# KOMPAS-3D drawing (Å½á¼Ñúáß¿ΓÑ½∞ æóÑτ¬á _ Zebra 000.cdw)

Views: Разрез А-А, Вид 3, Диметрия, Вид 4
Referenced files in D:\работа\Чертежи\Компенсатор\Пламегаситель Свечка\: ДТК.a3d, Компенсатор.m3d, Колпак.m3d, Пламегаситель Свечка _ Zebra 000.cdw
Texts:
  Zebra 000
  Пламегаситель "Свечка"
  Александр
  Колпак
  Компенсатор
  Zebra 002
  ТДК
  Zebra 001
  Лит-Масса-Масштаб
  Материал-Предприятие
  Title Specification
  Body Specification ( left align )
  Body Specificaton ( centered )
  Поз.
  Кол.
  Приме-
  чание
  Таблица спецификации
  Чередниченко А.В.
  Zebra 000-
Dimensions and other numbers on the sheet: 4; 2; 1; 0; 1:1; 0,19; 18.06.2015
